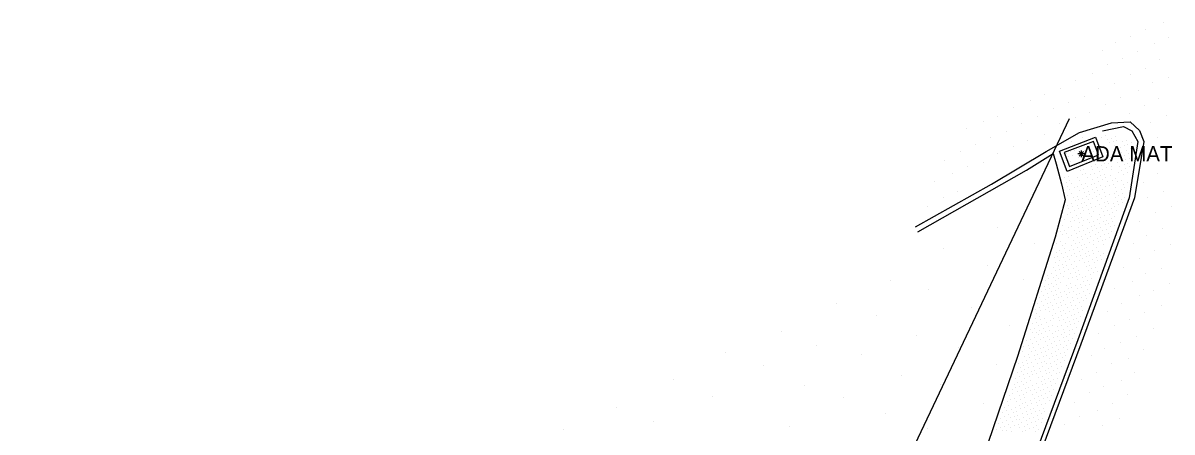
# Model space of a CAD drawing. Extents: x 1729983 to 1730242, y 468641 to 469019.
# Drawn here: x 1729998.3 to 1730133, y 468967.9 to 469015.9 of the extents above; entities that cross this region are included whole.
import ezdxf

# ---------------------------------------------------------------- set-up
doc = ezdxf.new("R2010")
doc.units = 0
for name, color, linetype in [('Default', 7, 'Continuous'), ('S_Curb_Type_1', 7, 'Continuous'), ('S_Curb_Type_2', 7, 'Continuous'), ('S_Ground_SpotElevation', 7, 'Continuous'), ('S_Misc_MiscFeature', 7, 'Continuous'), ('S_Misc_MiscItems', 7, 'Continuous'), ('S_Property_ConcPad', 7, 'Continuous'), ('S_Roadway_Edge_Pavement', 7, 'Continuous'), ('S_Roadway_Sidewalks', 7, 'Continuous'), ('S_Text', 7, 'Continuous'), ('S_Utilities_AG_Communications', 7, 'Continuous')]:
    doc.layers.add(name, color=color, linetype=linetype)

# ---------------------------------------------------------------- blocks, each defined once
blk = doc.blocks.new('POINT_DISPLAY')
at = {"layer": 'Default'}
blk.add_line((0, 0), (0, 0), dxfattribs=at)

msp = doc.modelspace()

# ---------------------------------------------------------------- linework, layer by layer
at = {"layer": 'S_Curb_Type_1'}
msp.add_lwpolyline([(1730127.34, 469003.74), (1730128.31, 469003.21), (1730129, 469001.96), (1730128, 468995.34), (1730121.97, 468978.7), (1730114.88, 468959.64), (1730107.95, 468940.79), (1730100.67, 468921.3), (1730089.46, 468890.12), (1730080.18, 468865.23), (1730072.81, 468845.37), (1730066.17, 468827.34), (1730059.27, 468808.01), (1730050.41, 468784.19), (1730032.96, 468736.85), (1730026.6, 468719.52), (1730017.93, 468696.12)], dxfattribs=at)
at = {"layer": 'S_Curb_Type_2'}
msp.add_line((1730124.88, 469003.23), (1730127.34, 469003.74), dxfattribs=at)
msp.add_lwpolyline([(1730103.21, 468991.38), (1730115.96, 468998.62), (1730119.08, 469000.57)], dxfattribs=at)
at = {"layer": 'S_Misc_MiscFeature'}
msp.add_lwpolyline([(1730124.41, 469000.39), (1730123.8, 469001.96), (1730120.39, 469000.66), (1730120.99, 468999.05), (1730124.41, 469000.39)], dxfattribs=at)
at = {"layer": 'S_Misc_MiscItems'}
for p, q in [((1730122.77, 469000.52), (1730121.99, 469000.52)), ((1730122.64, 469000.26), (1730122.12, 469000.78)), ((1730122.64, 469000.78), (1730122.12, 469000.26)), ((1730122.38, 469000.91), (1730122.38, 469000.13))]:
    msp.add_line(p, q, dxfattribs=at)
at = {"layer": 'S_Property_ConcPad'}
msp.add_lwpolyline([(1730124.92, 469000.16), (1730120.71, 468998.46), (1730119.81, 469000.83), (1730124.05, 469002.46), (1730124.92, 469000.16)], dxfattribs=at)
at = {"layer": 'S_Roadway_Edge_Pavement'}
for points in [[(1730102.95, 468991.96), (1730111.84, 468996.96), (1730118.27, 469000.8), (1730122.17, 469003.04), (1730125.91, 469004.15), (1730128.13, 469004.28), (1730129.22, 469003.24), (1730129.7, 469001.98), (1730128.62, 468995.34)], [(1730128.62, 468995.34), (1730122.32, 468978.18), (1730114.72, 468957.61), (1730108.47, 468940.56), (1730101.99, 468923.26), (1730100.18, 468918.25), (1730089.85, 468889.62), (1730080.62, 468864.76), (1730073.33, 468845.31), (1730066.51, 468826.62), (1730059.61, 468807.46), (1730050.88, 468783.51), (1730042.11, 468759.91), (1730034.56, 468739.83), (1730031.89, 468732.69), (1730026.74, 468718.51), (1730018.43, 468695.9)]]:
    msp.add_lwpolyline(points, dxfattribs=at)
at = {"layer": 'S_Roadway_Sidewalks'}
msp.add_lwpolyline([(1730119.08, 469000.57), (1730119.45, 468999.33), (1730120.06, 468996.99), (1730120.5, 468995.12), (1730119.3, 468990.74), (1730114.9, 468976.74), (1730109.15, 468959.85), (1730103.64, 468945.34), (1730096.17, 468925.75), (1730091, 468911.7), (1730089.34, 468910.17), (1730081.67, 468911.6)], dxfattribs=at)
at = {"layer": 'S_Utilities_AG_Communications'}
msp.add_lwpolyline([(1730120.95, 469004.63), (1730097.18, 468954.41), (1730085.56, 468926.55), (1730082.3, 468910.96), (1730034.66, 468781.32), (1729998.25, 468703.26)], dxfattribs=at)

# ---------------------------------------------------------------- block references
at = {"layer": 'S_Ground_SpotElevation'}
for p in [(1730131.99, 469015.88), (1730129.96, 469015.16), (1730126.36, 469013.56), (1730128.13, 469014.25), (1730130.93, 469013.42), (1730132.58, 469014.22), (1730124.81, 469012.65), (1730129.02, 469012.48), (1730125.48, 469010.96), (1730127.22, 469011.69), (1730129.91, 469010.5), (1730131.58, 469011.56), (1730121.67, 469009.16), (1730123.68, 469009.94), (1730128.14, 469009.83), (1730132.56, 469009.53), (1730119.97, 469008.22), (1730124.42, 469008.19), (1730126.31, 469008.83), (1730129.07, 469008.01), (1730130.71, 469008.9), (1730116.48, 469006.81), (1730118.07, 469007.48), (1730120.86, 469006.5), (1730122.79, 469007.22), (1730125.27, 469006.33), (1730126.97, 469007.14), (1730131.48, 469006.97), (1730114.44, 469005.93), (1730119.07, 469005.8), (1730123.38, 469005.34), (1730128.07, 469005.22), (1730129.79, 469006.17), (1730132.36, 469005.04), (1730110.91, 469004.29), (1730112.57, 469004.94), (1730115.31, 469004.13), (1730117.22, 469004.88), (1730119.85, 469004.05), (1730121.71, 469004.74), (1730130.54, 469004.22), (1730108.97, 469003.45), (1730111.74, 469002.49), (1730113.56, 469003.19), (1730118.01, 469002.78), (1730122.54, 469002.44), (1730124.72, 469002.42), (1730125.24, 469002.62), (1730125.95, 469002.32), (1730126.37, 469002.58), (1730131.36, 469002.49), (1730109.97, 469001.65), (1730114.48, 469001.36), (1730116.09, 469002.08), (1730121.24, 469001.92), (1730121.63, 469000.94), (1730122.13, 469001.12), (1730122.78, 469000.92), (1730123.2, 469001.22), (1730125.4, 469001.01), (1730125.41, 469002.16), (1730125.67, 469001.8), (1730126.1, 469001.94), (1730126.26, 469001.48), (1730126.54, 469002.09), (1730126.96, 469001.27), (1730127.24, 469001.92), (1730127.4, 469001.44), (1730127.65, 469000.96), (1730127.71, 469002.11), (1730127.83, 469001.66), (1730128.17, 469001.18), (1730128.32, 469001.84), (1730106.33, 468999.78), (1730108.21, 469000.79), (1730112.54, 469000.52), (1730120.69, 469000.5), (1730120.9, 469000.17), (1730121.08, 468999.67), (1730121.14, 469000.75), (1730121.33, 469000.31), (1730122.09, 469000.07), (1730122.49, 469000.28), (1730123.03, 469000.49), (1730123.22, 469000.07), (1730123.36, 469000.72), (1730123.58, 469000.17), (1730123.83, 469000.83), (1730125.59, 469000.61), (1730125.84, 469000.1), (1730126.14, 469000.76), (1730126.74, 469000.59), (1730127.02, 469000.09), (1730127.15, 469000.73), (1730127.21, 468999.65), (1730127.43, 469000.3), (1730127.56, 468999.85), (1730127.9, 469000.52), (1730128.08, 469000.02), (1730130.49, 469000.02), (1730132.39, 469000.79), (1730109.07, 468999.01), (1730110.9, 468999.56), (1730122.23, 468998.53), (1730122.66, 468998.7), (1730122.92, 468998.22), (1730123.61, 468999.08), (1730123.74, 468998.65), (1730124.1, 468999.28), (1730124.27, 468998.86), (1730124.48, 468998.44), (1730124.73, 468999.12), (1730124.88, 468998.66), (1730125.16, 468999.36), (1730125.32, 468998.9), (1730125.58, 468999.42), (1730125.87, 468998.99), (1730125.98, 468998.64), (1730126.68, 468999.52), (1730126.75, 468998.32), (1730126.91, 468998.98), (1730127.11, 468998.53), (1730127.45, 468999.21), (1730127.57, 468998.78), (1730127.78, 468999.43), (1730127.84, 468998.31), (1730127.98, 468998.98), (1730105.21, 468997.3), (1730107.26, 468998.18), (1730120.4, 468997.69), (1730120.64, 468997.16), (1730120.89, 468997.9), (1730121.03, 468997.39), (1730121.28, 468997), (1730121.97, 468997.78), (1730122.2, 468997.35), (1730122.43, 468996.9), (1730122.47, 468998.04), (1730122.91, 468997.09), (1730123.05, 468997.79), (1730123.51, 468998.06), (1730123.54, 468996.89), (1730123.71, 468997.52), (1730123.95, 468997.04), (1730123.98, 468998.19), (1730124.25, 468997.75), (1730124.42, 468997.24), (1730124.62, 468997.95), (1730124.9, 468997.46), (1730125.08, 468998.13), (1730125.26, 468997.77), (1730125.47, 468997.31), (1730125.79, 468997.95), (1730126, 468997.4), (1730126.19, 468996.94), (1730126.45, 468997.62), (1730126.67, 468997.27), (1730127.06, 468997.41), (1730127.31, 468998.07), (1730127.34, 468996.96), (1730127.78, 468997.15), (1730129.67, 468997.11), (1730131.29, 468998.18), (1730107.85, 468996.15), (1730120.75, 468996.73), (1730120.78, 468995.62), (1730120.98, 468996.29), (1730121.28, 468995.89), (1730121.53, 468996.51), (1730121.92, 468995.56), (1730121.99, 468996.67), (1730122.12, 468996.19), (1730122.62, 468996.45), (1730122.76, 468996), (1730123.03, 468995.54), (1730123.09, 468996.71), (1730123.25, 468996.15), (1730123.39, 468995.78), (1730123.74, 468996.35), (1730123.94, 468995.98), (1730124.15, 468996.6), (1730124.34, 468996.17), (1730124.5, 468995.7), (1730124.66, 468996.84), (1730124.85, 468996.31), (1730125.05, 468995.95), (1730125.21, 468995.54), (1730125.26, 468996.63), (1730125.67, 468996.84), (1730125.72, 468995.71), (1730126.23, 468995.87), (1730126.38, 468996.51), (1730126.56, 468996.05), (1730126.77, 468995.67), (1730127.06, 468996.29), (1730127.24, 468995.84), (1730127.5, 468996.52), (1730132.08, 468996.04), (1730104.4, 468994.35), (1730106.23, 468995.37), (1730120.72, 468994.51), (1730121.18, 468994.69), (1730121.36, 468994.31), (1730121.47, 468995.43), (1730121.66, 468995), (1730121.91, 468994.46), (1730122.09, 468995.13), (1730122.36, 468994.66), (1730122.51, 468995.29), (1730122.53, 468994.2), (1730122.72, 468994.85), (1730123, 468994.47), (1730123.22, 468995.13), (1730123.44, 468994.65), (1730123.58, 468994.2), (1730123.71, 468995.29), (1730124.05, 468994.34), (1730124.18, 468995.46), (1730124.34, 468995.03), (1730124.57, 468994.58), (1730124.76, 468995.31), (1730125.06, 468994.84), (1730125.19, 468994.31), (1730125.47, 468994.96), (1730125.63, 468994.63), (1730126.13, 468994.71), (1730126.3, 468994.37), (1730126.38, 468995.38), (1730126.58, 468994.93), (1730126.8, 468994.58), (1730127.07, 468995.19), (1730127.18, 468994.78), (1730127.41, 468995.41), (1730130.18, 468995.37), (1730132.99, 468994.32), (1730120.71, 468993.45), (1730120.87, 468994.06), (1730121.15, 468993.61), (1730121.35, 468993.07), (1730121.56, 468993.86), (1730121.76, 468993.31), (1730122.03, 468992.87), (1730122.04, 468994.06), (1730122.34, 468993.57), (1730122.42, 468993.1), (1730122.68, 468993.83), (1730123.2, 468993.98), (1730123.35, 468993.57), (1730123.53, 468993.11), (1730123.78, 468993.72), (1730124.31, 468992.86), (1730124.53, 468993.45), (1730124.67, 468993.06), (1730124.72, 468994.14), (1730125, 468993.75), (1730125.1, 468993.29), (1730125.46, 468993.88), (1730125.64, 468993.4), (1730125.88, 468992.98), (1730125.92, 468994.11), (1730126.01, 468993.62), (1730126.23, 468993.17), (1730126.5, 468993.91), (1730131.11, 468993.64), (1730112.56, 468991.86), (1730120.13, 468992.06), (1730120.39, 468991.57), (1730120.45, 468992.78), (1730120.88, 468991.84), (1730121.15, 468992.54), (1730121.27, 468991.98), (1730121.55, 468992.66), (1730121.6, 468991.57), (1730122.04, 468991.83), (1730122.17, 468992.46), (1730122.47, 468992.05), (1730122.6, 468991.55), (1730122.63, 468992.67), (1730123.13, 468992.8), (1730123.13, 468991.71), (1730123.36, 468992.42), (1730123.61, 468991.95), (1730123.75, 468991.5), (1730123.87, 468992.62), (1730123.98, 468992.16), (1730124.18, 468991.73), (1730124.51, 468992.31), (1730124.64, 468991.92), (1730124.87, 468991.54), (1730124.96, 468992.6), (1730125.17, 468992.19), (1730125.34, 468991.62), (1730125.39, 468992.72), (1730125.6, 468992.38), (1730125.76, 468991.94), (1730126.05, 468992.61), (1730126.22, 468992.15), (1730129.23, 468992.57), (1730131.92, 468991.73), (1730119.93, 468991.38), (1730119.93, 468990.22), (1730120.2, 468991), (1730120.61, 468991.22), (1730120.86, 468990.71), (1730121.24, 468990.93), (1730121.46, 468990.4), (1730121.8, 468991.14), (1730121.89, 468990.69), (1730122.13, 468990.16), (1730122.18, 468991.37), (1730122.43, 468990.8), (1730122.57, 468990.47), (1730122.92, 468991.03), (1730123.13, 468990.6), (1730123.33, 468991.26), (1730123.33, 468990.14), (1730123.51, 468990.81), (1730123.78, 468990.38), (1730124.05, 468991.07), (1730124.25, 468990.6), (1730124.41, 468991.3), (1730124.41, 468990.18), (1730124.67, 468990.87), (1730124.81, 468990.37), (1730125.1, 468991), (1730125.25, 468990.5), (1730125.52, 468991.18), (1730125.69, 468990.74), (1730125.95, 468991.45), (1730130.01, 468990.88), (1730106.25, 468989.43), (1730116.95, 468990.03), (1730119.44, 468988.88), (1730119.49, 468990.01), (1730119.88, 468989.19), (1730120.14, 468989.81), (1730120.37, 468989.41), (1730120.52, 468990.05), (1730120.53, 468988.93), (1730121, 468989.18), (1730121.2, 468989.74), (1730121.44, 468989.27), (1730121.62, 468988.87), (1730121.68, 468990.05), (1730121.89, 468989.49), (1730122.15, 468989.1), (1730122.36, 468989.78), (1730122.57, 468989.33), (1730122.8, 468989.92), (1730122.84, 468988.85), (1730123.02, 468989.55), (1730123.2, 468989.05), (1730123.67, 468989.21), (1730123.87, 468989.92), (1730124.17, 468989.5), (1730124.38, 468989.06), (1730125, 468989.9), (1730125.03, 468988.82), (1730128.46, 468989.96), (1730130.98, 468989.15), (1730132.84, 468989.88), (1730111.34, 468987.45), (1730119.22, 468988.29), (1730119.4, 468987.76), (1730119.64, 468988.48), (1730119.81, 468987.99), (1730120.09, 468988.78), (1730120.14, 468987.58), (1730120.3, 468988.32), (1730120.56, 468987.84), (1730120.71, 468988.45), (1730121.01, 468988.08), (1730121.2, 468987.49), (1730121.24, 468988.6), (1730121.64, 468987.84), (1730121.83, 468988.41), (1730122.13, 468988), (1730122.27, 468988.64), (1730122.49, 468988.21), (1730122.76, 468987.79), (1730123.03, 468988.45), (1730123.24, 468987.9), (1730123.38, 468988.57), (1730123.38, 468987.46), (1730123.68, 468988.14), (1730123.84, 468988.78), (1730123.93, 468987.73), (1730124.15, 468988.39), (1730124.31, 468987.95), (1730124.61, 468988.57), (1730124.73, 468988.17), (1730129.17, 468988.18), (1730118.43, 468986.25), (1730118.9, 468986.48), (1730119.08, 468987.21), (1730119.3, 468986.77), (1730119.52, 468986.29), (1730119.68, 468987.39), (1730119.86, 468986.93), (1730119.97, 468986.46), (1730120.26, 468987.22), (1730120.44, 468986.75), (1730120.68, 468987.38), (1730120.9, 468986.96), (1730121.1, 468986.45), (1730121.41, 468987.06), (1730121.67, 468986.64), (1730121.77, 468986.13), (1730121.86, 468987.3), (1730122.05, 468986.81), (1730122.2, 468986.41), (1730122.86, 468986.13), (1730123.01, 468987.24), (1730123.21, 468986.8), (1730123.42, 468986.34), (1730123.62, 468987.01), (1730123.82, 468986.62), (1730124.1, 468987.2), (1730124.25, 468986.76), (1730127.32, 468987.23), (1730129.95, 468986.5), (1730131.77, 468987.11), (1730100.04, 468985.61), (1730115.63, 468985.82), (1730118.01, 468984.97), (1730118.17, 468985.62), (1730118.48, 468985.22), (1730118.58, 468985.85), (1730118.86, 468985.35), (1730119.1, 468985), (1730119.16, 468986.04), (1730119.35, 468985.63), (1730119.53, 468985.15), (1730119.71, 468985.83), (1730119.92, 468985.37), (1730120.3, 468986.06), (1730120.68, 468985.1), (1730120.89, 468985.85), (1730121.12, 468985.3), (1730121.28, 468984.8), (1730121.3, 468985.95), (1730121.73, 468985.03), (1730121.97, 468985.8), (1730122.24, 468985.21), (1730122.4, 468984.78), (1730122.53, 468985.98), (1730122.61, 468985.54), (1730122.83, 468985.02), (1730123.08, 468985.68), (1730123.33, 468985.21), (1730123.62, 468985.9), (1730128.33, 468985.48), (1730132.77, 468985.34), (1730104.48, 468984.63), (1730117.48, 468983.62), (1730117.68, 468984.31), (1730117.96, 468983.84), (1730118.13, 468983.44), (1730118.19, 468984.54), (1730118.41, 468984.12), (1730118.57, 468983.64), (1730118.6, 468984.71), (1730118.86, 468984.31), (1730119.1, 468983.83), (1730119.26, 468983.41), (1730119.34, 468984.46), (1730119.53, 468984.03), (1730119.67, 468983.64), (1730119.7, 468984.71), (1730119.96, 468984.28), (1730120.09, 468983.8), (1730120.43, 468984.39), (1730120.65, 468984.01), (1730120.81, 468983.6), (1730120.86, 468984.67), (1730121.03, 468984.23), (1730121.3, 468983.68), (1730121.49, 468984.35), (1730121.79, 468983.98), (1730121.96, 468983.49), (1730121.99, 468984.7), (1730122.19, 468984.17), (1730122.43, 468983.69), (1730122.62, 468984.37), (1730122.86, 468983.85), (1730123.03, 468983.52), (1730123.09, 468984.56), (1730123.29, 468984.14), (1730126.3, 468984.72), (1730129.17, 468983.91), (1730130.88, 468984.47), (1730093.65, 468982.91), (1730109.5, 468982.42), (1730117.01, 468982.26), (1730117.26, 468982.98), (1730117.47, 468982.47), (1730117.62, 468982.08), (1730117.72, 468983.23), (1730117.96, 468982.75), (1730118.17, 468982.3), (1730118.38, 468982.96), (1730118.57, 468982.49), (1730118.75, 468983.1), (1730119.03, 468982.7), (1730119.17, 468982.28), (1730119.43, 468982.92), (1730119.67, 468982.5), (1730119.89, 468982.05), (1730119.94, 468983.08), (1730120.06, 468982.69), (1730120.32, 468982.14), (1730120.35, 468983.27), (1730120.57, 468982.84), (1730120.75, 468982.42), (1730121.08, 468983.05), (1730121.21, 468982.66), (1730121.42, 468982.22), (1730121.45, 468983.27), (1730121.7, 468982.77), (1730121.9, 468982.35), (1730122.16, 468983.11), (1730122.42, 468982.59), (1730122.53, 468982.15), (1730122.59, 468983.26), (1730127.07, 468982.97), (1730131.79, 468982.66), (1730098.34, 468981.48), (1730116.97, 468981.14), (1730117.15, 468981.8), (1730117.45, 468981.37), (1730117.58, 468981.04), (1730118.09, 468981.22), (1730118.71, 468981.99), (1730118.8, 468980.9), (1730118.96, 468981.56), (1730119.15, 468981.13), (1730119.39, 468981.74), (1730119.66, 468981.29), (1730119.83, 468980.96), (1730120.09, 468981.48), (1730120.29, 468981.06), (1730120.49, 468981.82), (1730120.78, 468981.27), (1730120.94, 468980.88), (1730121.03, 468982.01), (1730121.21, 468981.5), (1730121.47, 468981.03), (1730121.63, 468981.7), (1730121.84, 468981.24), (1730122.01, 468980.86), (1730122.05, 468981.91), (1730122.24, 468981.47), (1730125.45, 468982.04), (1730128.02, 468981.07), (1730129.81, 468981.89), (1730087.23, 468979.66), (1730114.01, 468980.42), (1730116.45, 468979.91), (1730116.65, 468980.61), (1730116.65, 468979.5), (1730116.85, 468980.04), (1730117.09, 468979.59), (1730117.14, 468980.7), (1730117.41, 468980.35), (1730117.51, 468979.83), (1730117.72, 468979.45), (1730117.77, 468980.53), (1730117.99, 468980), (1730118.21, 468979.67), (1730118.32, 468980.67), (1730118.54, 468980.22), (1730118.66, 468979.74), (1730118.96, 468979.39), (1730118.98, 468980.42), (1730119.39, 468979.61), (1730119.54, 468980.28), (1730119.73, 468979.78), (1730120.09, 468980.42), (1730120.25, 468979.93), (1730120.39, 468979.53), (1730120.51, 468980.68), (1730120.74, 468980.2), (1730120.96, 468979.75), (1730121.15, 468980.44), (1730121.39, 468979.95), (1730121.57, 468979.44), (1730121.59, 468980.57), (1730121.81, 468980.13), (1730124.39, 468979.38), (1730126.22, 468980.35), (1730130.8, 468979.99), (1730091.29, 468978.04), (1730103.1, 468979.19), (1730115.99, 468978.6), (1730116.18, 468978.03), (1730116.48, 468978.77), (1730116.61, 468978.24), (1730116.94, 468978.94), (1730117.07, 468978.52), (1730117.32, 468979.25), (1730117.33, 468978.12), (1730117.59, 468978.69), (1730117.98, 468979), (1730118.23, 468978.46), (1730118.44, 468979.09), (1730118.47, 468978.01), (1730118.64, 468978.7), (1730118.89, 468978.2), (1730119.12, 468978.94), (1730119.27, 468978.49), (1730119.46, 468978.03), (1730119.63, 468979.11), (1730119.81, 468978.63), (1730119.99, 468978.16), (1730120.02, 468979.28), (1730120.25, 468978.91), (1730120.44, 468978.43), (1730120.65, 468979.12), (1730120.92, 468978.65), (1730121.05, 468979.28), (1730121.07, 468978.22), (1730121.3, 468978.81), (1730126.98, 468978.35), (1730128.86, 468979.11), (1730080.62, 468977.2), (1730096.59, 468976.91), (1730107.94, 468977.73), (1730115.51, 468977.28), (1730115.66, 468977.92), (1730115.73, 468976.78), (1730116.16, 468976.98), (1730116.33, 468977.71), (1730116.54, 468977.26), (1730116.79, 468977.81), (1730116.84, 468976.8), (1730116.97, 468977.39), (1730117.27, 468977), (1730117.55, 468977.63), (1730117.71, 468977.2), (1730117.91, 468976.69), (1730117.92, 468977.78), (1730118.13, 468977.31), (1730118.3, 468976.88), (1730118.56, 468977.56), (1730118.85, 468977.12), (1730119, 468976.71), (1730119.05, 468977.78), (1730119.31, 468977.29), (1730119.48, 468976.81), (1730119.71, 468977.54), (1730119.98, 468977.1), (1730120.24, 468977.75), (1730120.45, 468977.25), (1730120.56, 468976.82), (1730120.6, 468977.96), (1730120.82, 468977.57), (1730123.62, 468976.84), (1730125.12, 468977.66), (1730129.71, 468977.54), (1730085.06, 468975.63), (1730112.48, 468975.78), (1730115.01, 468975.91), (1730115.23, 468975.46), (1730115.46, 468976.07), (1730115.66, 468975.62), (1730115.91, 468976.31), (1730116.03, 468975.9), (1730116.24, 468975.44), (1730116.32, 468976.56), (1730116.52, 468976.07), (1730116.73, 468975.58), (1730117.05, 468976.32), (1730117.23, 468975.85), (1730117.46, 468975.36), (1730117.51, 468976.52), (1730117.73, 468976.06), (1730117.88, 468975.59), (1730118.12, 468976.19), (1730118.31, 468975.86), (1730118.6, 468976.51), (1730118.75, 468975.96), (1730118.92, 468975.52), (1730119.28, 468976.16), (1730119.5, 468975.76), (1730119.63, 468976.42), (1730119.92, 468975.97), (1730120.1, 468975.55), (1730120.18, 468976.6), (1730120.39, 468976.21), (1730125.98, 468975.92), (1730127.96, 468976.49), (1730074.59, 468974), (1730101.35, 468974.47), (1730114.68, 468974.14), (1730114.9, 468974.83), (1730115.15, 468974.41), (1730115.33, 468974.96), (1730115.61, 468974.58), (1730115.77, 468975.22), (1730115.77, 468974.12), (1730116.11, 468974.73), (1730116.29, 468974.35), (1730116.51, 468975.01), (1730116.69, 468974.58), (1730116.92, 468975.11), (1730117.12, 468974.73), (1730117.41, 468974.29), (1730117.56, 468974.92), (1730117.8, 468974.41), (1730118.06, 468974.02), (1730118.13, 468975.1), (1730118.33, 468974.67), (1730118.52, 468974.18), (1730118.57, 468975.28), (1730118.68, 468974.84), (1730118.92, 468974.48), (1730119.14, 468975.11), (1730119.15, 468974.01), (1730119.44, 468974.68), (1730119.58, 468974.17), (1730119.59, 468975.28), (1730119.81, 468974.9), (1730122.37, 468973.99), (1730124.21, 468974.83), (1730128.65, 468974.87), (1730089.96, 468973.35), (1730105.89, 468973.47), (1730114.26, 468972.83), (1730114.5, 468973.47), (1730114.65, 468973.08), (1730114.86, 468972.63), (1730114.88, 468973.71), (1730115.08, 468973.17), (1730115.33, 468973.81), (1730115.38, 468972.73), (1730115.63, 468973.42), (1730115.79, 468972.97), (1730115.98, 468973.64), (1730116.24, 468973.14), (1730116.39, 468972.68), (1730116.46, 468973.88), (1730116.65, 468973.33), (1730116.85, 468972.9), (1730117.16, 468973.58), (1730117.33, 468973.13), (1730117.62, 468972.68), (1730117.67, 468973.81), (1730117.84, 468973.42), (1730118, 468972.87), (1730118.23, 468973.56), (1730118.4, 468973.13), (1730118.62, 468972.63), (1730118.78, 468973.75), (1730118.84, 468973.31), (1730119.07, 468972.84), (1730119.31, 468973.52), (1730124.97, 468973.17), (1730127.08, 468973.89), (1730079.17, 468972.02), (1730094.46, 468971.87), (1730113.68, 468971.43), (1730113.96, 468972.09), (1730114.1, 468971.71), (1730114.34, 468972.35), (1730114.58, 468971.83), (1730114.79, 468971.43), (1730115.08, 468972.11), (1730115.28, 468971.7), (1730115.58, 468972.32), (1730115.74, 468971.88), (1730115.88, 468971.37), (1730115.98, 468972.5), (1730116.45, 468971.58), (1730116.68, 468972.24), (1730116.84, 468971.83), (1730117.08, 468971.37), (1730117.15, 468972.5), (1730117.31, 468972.08), (1730117.49, 468971.55), (1730117.74, 468972.17), (1730117.96, 468971.77), (1730118.18, 468972.42), (1730118.37, 468971.93), (1730118.62, 468971.53), (1730118.86, 468972.12), (1730121.55, 468971.37), (1730123.31, 468972.49), (1730127.78, 468972.3), (1730067.86, 468970.77), (1730099.4, 468969.98), (1730110.86, 468971.25), (1730113.18, 468970.16), (1730113.41, 468970.76), (1730113.62, 468970.34), (1730113.88, 468971.03), (1730114.16, 468970.55), (1730114.38, 468970.16), (1730114.62, 468970.73), (1730114.79, 468970.25), (1730115.08, 468971), (1730115.25, 468970.58), (1730115.47, 468971.21), (1730115.52, 468970.06), (1730115.76, 468970.71), (1730115.94, 468970.25), (1730116.08, 468970.92), (1730116.42, 468970.52), (1730116.52, 468970.04), (1730116.57, 468971.19), (1730116.81, 468970.67), (1730116.96, 468970.25), (1730117.22, 468970.95), (1730117.49, 468970.39), (1730117.7, 468970.05), (1730117.73, 468971.14), (1730117.98, 468970.6), (1730118.09, 468970.22), (1730118.18, 468971.25), (1730124.27, 468970.42), (1730126, 468971.2), (1730072.15, 468969.12), (1730112.7, 468968.85), (1730112.96, 468969.49), (1730113.15, 468969.03), (1730113.41, 468969.68), (1730113.56, 468969.23), (1730113.83, 468968.75), (1730113.86, 468969.86), (1730114.1, 468969.52), (1730114.3, 468969.07), (1730114.54, 468968.59), (1730114.6, 468969.66), (1730114.76, 468969.27), (1730114.94, 468969.85), (1730114.98, 468968.71), (1730115.19, 468969.34), (1730115.36, 468968.94), (1730115.6, 468969.62), (1730115.92, 468969.16), (1730116.06, 468968.78), (1730116.09, 468969.9), (1730116.31, 468969.45), (1730116.56, 468968.99), (1730116.78, 468969.51), (1730117.04, 468969.14), (1730117.14, 468968.63), (1730117.23, 468969.79), (1730117.38, 468969.37), (1730117.7, 468968.92), (1730117.84, 468969.49), (1730120.44, 468968.78), (1730122.17, 468969.63), (1730124.83, 468968.65), (1730126.82, 468969.48), (1730061.66, 468968.15), (1730088.14, 468968.52), (1730104.38, 468968.3), (1730112.45, 468968.17), (1730112.94, 468968.33), (1730113.12, 468967.98), (1730113.37, 468968.54), (1730113.56, 468968.08), (1730114.08, 468968.34), (1730114.23, 468967.91), (1730115.13, 468968.33), (1730115.43, 468967.86), (1730115.68, 468968.54), (1730115.79, 468968), (1730116.33, 468968.25), (1730116.73, 468968.44), (1730116.96, 468967.96), (1730117.38, 468968.14)]:
    msp.add_blockref('POINT_DISPLAY', p, dxfattribs=at)

# ---------------------------------------------------------------- texts
at = {"layer": 'S_Text'}
msp.add_text('ADA MAT', height=1.8, dxfattribs=at).set_placement((1730122.38, 468999.62))

doc.saveas('drawing.dxf')
